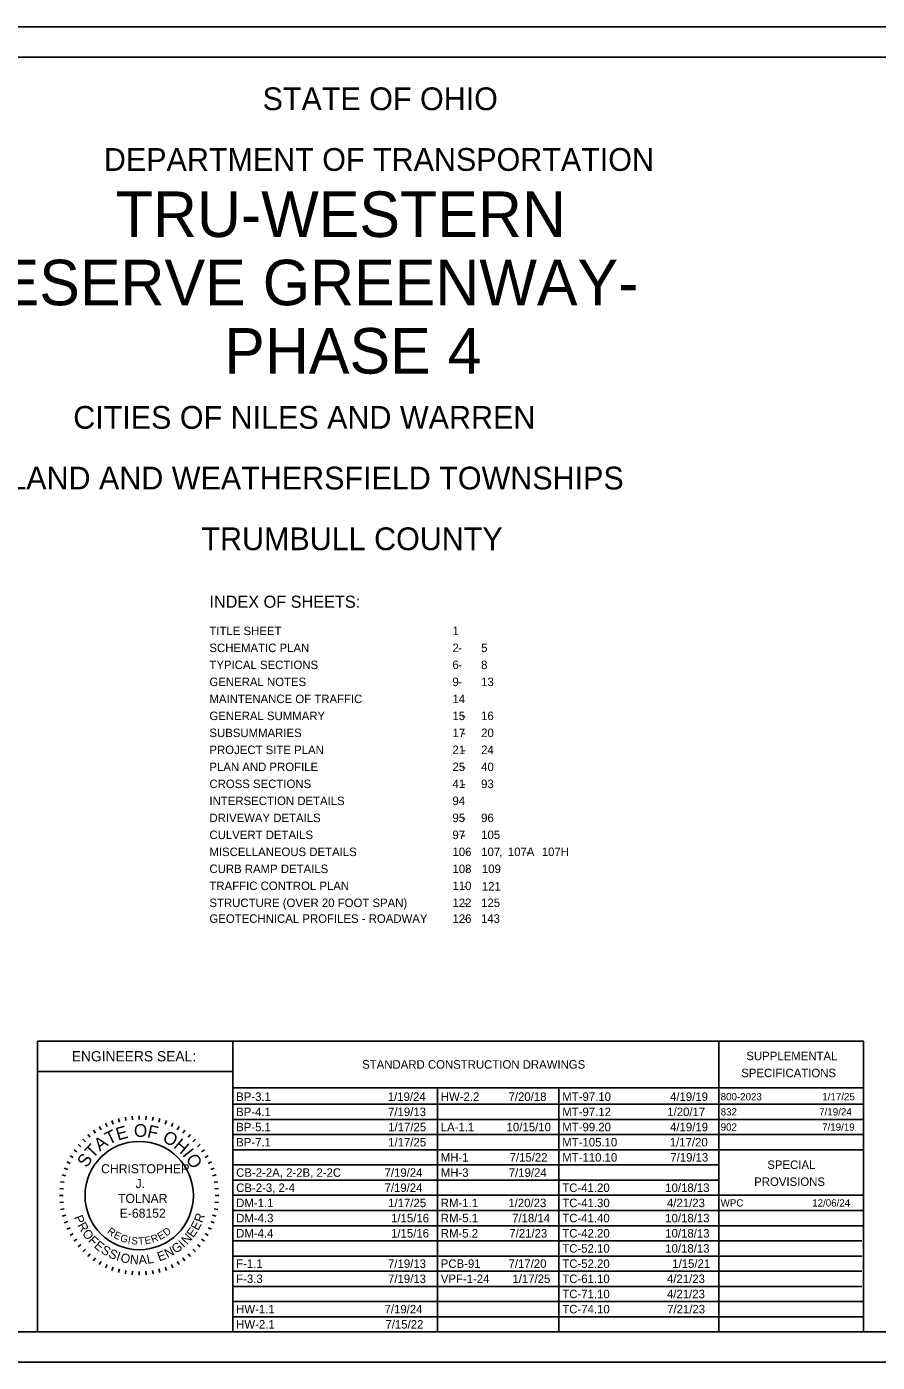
# Model space of a CAD drawing. Extents: x -37878.7 to -37844.7, y -19791.4 to -19769.4.
# Drawn here: x -37867.14 to -37853.14, y -19791.39 to -19769.39 of the extents above; entities that cross this region are included whole.
import ezdxf

# ---------------------------------------------------------------- set-up
doc = ezdxf.new("R2010")
doc.units = 0
for name, color, linetype in [('SH_Border', 7, 'Continuous'), ('SH_Cut_Line', 7, 'Continuous'), ('SH_Data', 7, 'Continuous')]:
    doc.layers.add(name, color=color, linetype=linetype)

msp = doc.modelspace()

# ---------------------------------------------------------------- linework, layer by layer
at = {"layer": 'SH_Border'}
msp.add_lwpolyline([(-37876.65, -19769.885), (-37845.15, -19769.885), (-37845.15, -19790.885), (-37876.65, -19790.885)], close=True, dxfattribs=at)
at = {"layer": 'SH_Cut_Line'}
msp.add_lwpolyline([(-37878.65, -19791.385), (-37844.65, -19791.385), (-37844.65, -19769.385), (-37878.65, -19769.385)], close=True, dxfattribs=at)
at = {"layer": 'SH_Data'}
for p, q in [((-37866.964, -19786.094), (-37863.748, -19786.094)), ((-37866.964, -19787.635), (-37866.964, -19786.094)), ((-37863.748, -19786.094), (-37853.365, -19786.094)), ((-37863.748, -19790.885), (-37863.748, -19786.094)), ((-37855.748, -19790.885), (-37855.748, -19786.094)), ((-37853.365, -19790.885), (-37853.365, -19786.094)), ((-37866.964, -19786.594), (-37863.748, -19786.594)), ((-37863.748, -19786.864), (-37853.365, -19786.864)), ((-37860.38, -19790.885), (-37860.38, -19786.864)), ((-37858.38, -19790.885), (-37858.38, -19786.864)), ((-37863.748, -19787.135), (-37853.365, -19787.135)), ((-37865.844, -19787.449), (-37865.819, -19787.504)), ((-37865.738, -19787.405), (-37865.718, -19787.462)), ((-37865.629, -19787.371), (-37865.614, -19787.429)), ((-37865.517, -19787.346), (-37865.507, -19787.405)), ((-37865.404, -19787.331), (-37865.399, -19787.391)), ((-37865.289, -19787.326), (-37865.289, -19787.386)), ((-37865.175, -19787.331), (-37865.18, -19787.391)), ((-37865.061, -19787.346), (-37865.072, -19787.405)), ((-37864.95, -19787.371), (-37864.965, -19787.429)), ((-37864.84, -19787.405), (-37864.861, -19787.462)), ((-37864.735, -19787.449), (-37864.76, -19787.504)), ((-37863.748, -19787.385), (-37853.365, -19787.385)), ((-37866.964, -19790.885), (-37866.964, -19787.635)), ((-37866.133, -19787.633), (-37866.094, -19787.679)), ((-37866.042, -19787.564), (-37866.008, -19787.613)), ((-37865.946, -19787.502), (-37865.916, -19787.554)), ((-37864.633, -19787.502), (-37864.663, -19787.554)), ((-37864.537, -19787.564), (-37864.571, -19787.613)), ((-37864.446, -19787.633), (-37864.484, -19787.679)), ((-37863.748, -19787.635), (-37853.365, -19787.635)), ((-37866.364, -19787.886), (-37866.315, -19787.92)), ((-37866.295, -19787.795), (-37866.249, -19787.834)), ((-37866.217, -19787.711), (-37866.175, -19787.753)), ((-37864.361, -19787.711), (-37864.404, -19787.753)), ((-37864.284, -19787.795), (-37864.33, -19787.834)), ((-37864.214, -19787.886), (-37864.263, -19787.92)), ((-37863.748, -19787.885), (-37853.365, -19787.885)), ((-37866.479, -19788.084), (-37866.424, -19788.109)), ((-37866.426, -19787.982), (-37866.374, -19788.012)), ((-37864.153, -19787.982), (-37864.205, -19788.012)), ((-37864.1, -19788.084), (-37864.154, -19788.109)), ((-37866.557, -19788.299), (-37866.499, -19788.314)), ((-37866.523, -19788.19), (-37866.466, -19788.21)), ((-37864.056, -19788.19), (-37864.112, -19788.21)), ((-37864.022, -19788.299), (-37864.08, -19788.314)), ((-37863.748, -19788.135), (-37855.748, -19788.135)), ((-37866.597, -19788.524), (-37866.537, -19788.53)), ((-37866.582, -19788.411), (-37866.523, -19788.421)), ((-37863.997, -19788.411), (-37864.056, -19788.421)), ((-37863.982, -19788.524), (-37864.042, -19788.53)), ((-37863.748, -19788.385), (-37855.748, -19788.385)), ((-37866.602, -19788.639), (-37866.542, -19788.639)), ((-37866.597, -19788.753), (-37866.537, -19788.748)), ((-37863.982, -19788.753), (-37864.042, -19788.748)), ((-37863.977, -19788.639), (-37864.037, -19788.639)), ((-37863.748, -19788.635), (-37853.365, -19788.635)), ((-37866.582, -19788.867), (-37866.523, -19788.856)), ((-37866.557, -19788.978), (-37866.499, -19788.963)), ((-37864.022, -19788.978), (-37864.08, -19788.963)), ((-37863.997, -19788.867), (-37864.056, -19788.856)), ((-37863.748, -19788.885), (-37853.365, -19788.885)), ((-37866.523, -19789.088), (-37866.466, -19789.067)), ((-37866.479, -19789.193), (-37866.424, -19789.168)), ((-37864.1, -19789.193), (-37864.154, -19789.168)), ((-37864.056, -19789.088), (-37864.112, -19789.067)), ((-37863.748, -19789.135), (-37853.365, -19789.135)), ((-37866.426, -19789.295), (-37866.374, -19789.265)), ((-37866.364, -19789.391), (-37866.315, -19789.357)), ((-37864.214, -19789.391), (-37864.263, -19789.357)), ((-37864.153, -19789.295), (-37864.205, -19789.265)), ((-37863.748, -19789.385), (-37853.395, -19789.385)), ((-37866.295, -19789.482), (-37866.249, -19789.444)), ((-37866.217, -19789.567), (-37866.175, -19789.524)), ((-37866.133, -19789.644), (-37866.094, -19789.598)), ((-37864.446, -19789.644), (-37864.484, -19789.598)), ((-37864.361, -19789.567), (-37864.404, -19789.524)), ((-37864.284, -19789.482), (-37864.33, -19789.444)), ((-37863.748, -19789.635), (-37853.395, -19789.635)), ((-37866.042, -19789.714), (-37866.008, -19789.665)), ((-37865.946, -19789.775), (-37865.916, -19789.723)), ((-37865.844, -19789.828), (-37865.819, -19789.774)), ((-37865.738, -19789.872), (-37865.718, -19789.816)), ((-37865.629, -19789.906), (-37865.614, -19789.848)), ((-37865.517, -19789.931), (-37865.507, -19789.872)), ((-37865.061, -19789.931), (-37865.072, -19789.872)), ((-37864.95, -19789.906), (-37864.965, -19789.848)), ((-37864.84, -19789.872), (-37864.861, -19789.816)), ((-37864.735, -19789.828), (-37864.76, -19789.774)), ((-37864.633, -19789.775), (-37864.663, -19789.723)), ((-37864.537, -19789.714), (-37864.571, -19789.665)), ((-37865.404, -19789.946), (-37865.399, -19789.886)), ((-37865.289, -19789.951), (-37865.289, -19789.891)), ((-37865.175, -19789.946), (-37865.18, -19789.886)), ((-37863.748, -19789.885), (-37853.395, -19789.885)), ((-37863.748, -19790.135), (-37853.395, -19790.135)), ((-37863.748, -19790.385), (-37853.365, -19790.385)), ((-37863.748, -19790.635), (-37853.365, -19790.635))]:
    msp.add_line(p, q, dxfattribs=at)
msp.add_circle((-37865.289, -19788.639), 0.892, dxfattribs=at)

# ---------------------------------------------------------------- texts
for s, height, p in [('STATE OF OHIO', 0.375, (-37863.258, -19770.76)), ('DEPARTMENT OF TRANSPORTATION', 0.375, (-37865.87, -19771.76)), ('TRU-WESTERN', 0.75, (-37865.676, -19772.849)), ('RESERVE GREENWAY-', 0.75, (-37868.328, -19773.974)), ('PHASE 4', 0.75, (-37863.89, -19775.099)), ('CITIES OF NILES AND WARREN', 0.375, (-37866.375, -19776.008)), ('HOWLAND AND WEATHERSFIELD TOWNSHIPS', 0.375, (-37868.653, -19777.008)), ('TRUMBULL COUNTY', 0.375, (-37864.265, -19778.008)), ('INDEX OF SHEETS:', 0.2, (-37864.133, -19778.957)), ('TITLE SHEET', 0.14, (-37864.133, -19779.407)), ('1', 0.14, (-37860.133, -19779.407)), ('SCHEMATIC PLAN', 0.14, (-37864.133, -19779.687)), ('2', 0.14, (-37860.133, -19779.687)), ('   -', 0.14, (-37860.196, -19779.687)), ('5', 0.14, (-37859.661, -19779.687)), ('TYPICAL SECTIONS', 0.14, (-37864.133, -19779.967)), ('6', 0.14, (-37860.133, -19779.967)), ('   -', 0.14, (-37860.196, -19779.967)), ('8', 0.14, (-37859.661, -19779.967)), ('GENERAL NOTES', 0.14, (-37864.133, -19780.247)), ('9', 0.14, (-37860.133, -19780.247)), ('   -', 0.14, (-37860.196, -19780.247)), ('13', 0.14, (-37859.661, -19780.247)), ('MAINTENANCE OF TRAFFIC', 0.14, (-37864.133, -19780.527)), ('14', 0.14, (-37860.133, -19780.527)), ('GENERAL SUMMARY', 0.14, (-37864.133, -19780.807)), ('15', 0.14, (-37860.133, -19780.807)), ('   -', 0.14, (-37860.133, -19780.807)), ('16', 0.14, (-37859.661, -19780.807)), ('SUBSUMMARIES', 0.14, (-37864.133, -19781.087)), ('17', 0.14, (-37860.133, -19781.087)), ('   -', 0.14, (-37860.133, -19781.087)), ('20', 0.14, (-37859.661, -19781.087)), ('PROJECT SITE PLAN', 0.14, (-37864.133, -19781.367)), ('21', 0.14, (-37860.133, -19781.367)), ('24', 0.14, (-37859.661, -19781.367)), ('PLAN AND PROFILE', 0.14, (-37864.133, -19781.647)), ('25', 0.14, (-37860.133, -19781.647)), ('   -', 0.14, (-37860.133, -19781.367)), ('40', 0.14, (-37859.661, -19781.647)), ('   -', 0.14, (-37860.133, -19781.647)), ('CROSS SECTIONS', 0.14, (-37864.133, -19781.927)), ('41', 0.14, (-37860.133, -19781.927)), ('   -', 0.14, (-37860.133, -19781.927)), ('93', 0.14, (-37859.661, -19781.927)), ('INTERSECTION DETAILS', 0.14, (-37864.133, -19782.207)), ('94', 0.14, (-37860.133, -19782.207)), ('DRIVEWAY DETAILS', 0.14, (-37864.133, -19782.487)), ('95', 0.14, (-37860.133, -19782.487)), ('96', 0.14, (-37859.661, -19782.487)), ('   -', 0.14, (-37860.133, -19782.487)), ('CULVERT DETAILS', 0.14, (-37864.133, -19782.767)), ('97', 0.14, (-37860.133, -19782.767)), ('   -', 0.14, (-37860.133, -19782.767)), ('105', 0.14, (-37859.661, -19782.767)), ('MISCELLANEOUS DETAILS', 0.14, (-37864.133, -19783.047)), ('106', 0.14, (-37860.133, -19783.047)), ('   -', 0.14, (-37860.082, -19783.047)), ('107', 0.14, (-37859.659, -19783.047)), (',', 0.14, (-37859.364, -19783.047)), ('107A', 0.14, (-37859.221, -19783.047)), ('   -', 0.14, (-37859.077, -19783.047)), ('107H', 0.14, (-37858.663, -19783.047)), ('CURB RAMP DETAILS', 0.14, (-37864.133, -19783.327)), ('108', 0.14, (-37860.133, -19783.327)), ('   -', 0.14, (-37860.082, -19783.327)), ('109', 0.14, (-37859.648, -19783.327)), ('TRAFFIC CONTROL PLAN', 0.14, (-37864.133, -19783.607)), ('110', 0.14, (-37860.133, -19783.607)), ('121', 0.14, (-37859.648, -19783.615)), ('   -', 0.14, (-37860.107, -19783.607)), ('STRUCTURE (OVER 20 FOOT SPAN)', 0.14, (-37864.133, -19783.887)), ('122', 0.14, (-37860.133, -19783.887)), ('   -', 0.14, (-37860.105, -19783.887)), ('125', 0.14, (-37859.661, -19783.887)), ('GEOTECHNICAL PROFILES - ROADWAY', 0.14, (-37864.133, -19784.147)), ('126', 0.14, (-37860.133, -19784.147)), ('   -', 0.14, (-37860.103, -19784.147)), ('143', 0.14, (-37859.663, -19784.147)), ('ENGINEERS SEAL:', 0.17, (-37866.399, -19786.429)), ('SUPPLEMENTAL', 0.14, (-37855.295, -19786.409)), ('STANDARD CONSTRUCTION DRAWINGS', 0.14, (-37861.619, -19786.549)), ('SPECIFICATIONS', 0.14, (-37855.379, -19786.689)), ('BP-3.1', 0.14, (-37863.693, -19787.08)), ('1/19/24', 0.14, (-37861.198, -19787.08)), ('HW-2.2', 0.14, (-37860.325, -19787.08)), ('7/20/18', 0.14, (-37859.21, -19787.08)), ('MT-97.10', 0.14, (-37858.325, -19787.08)), ('4/19/19', 0.14, (-37856.551, -19787.08)), ('800-2023', 0.12, (-37855.718, -19787.07)), ('1/17/25', 0.12, (-37854.045, -19787.07)), ('BP-4.1', 0.14, (-37863.693, -19787.33)), ('7/19/13', 0.14, (-37861.193, -19787.33)), ('MT-97.12', 0.14, (-37858.325, -19787.33)), ('1/20/17', 0.14, (-37856.597, -19787.33)), ('832', 0.12, (-37855.718, -19787.32)), ('7/19/24', 0.12, (-37854.096, -19787.32)), ('BP-5.1', 0.14, (-37863.693, -19787.58)), ('1/17/25', 0.14, (-37861.191, -19787.58)), ('LA-1.1', 0.14, (-37860.325, -19787.58)), ('10/15/10', 0.14, (-37859.241, -19787.58)), ('MT-99.20', 0.14, (-37858.325, -19787.58)), ('4/19/19', 0.14, (-37856.551, -19787.58)), ('902', 0.12, (-37855.718, -19787.57)), ('7/19/19', 0.12, (-37854.048, -19787.57)), ('BP-7.1', 0.14, (-37863.693, -19787.83)), ('1/17/25', 0.14, (-37861.191, -19787.83)), ('MT-105.10', 0.14, (-37858.325, -19787.83)), ('1/17/20', 0.14, (-37856.556, -19787.83)), ('MH-1', 0.14, (-37860.325, -19788.08)), ('7/15/22', 0.14, (-37859.192, -19788.08)), ('MT-110.10', 0.14, (-37858.325, -19788.08)), ('7/19/13', 0.14, (-37856.547, -19788.08)), ('SPECIAL', 0.14, (-37854.95, -19788.201)), ('CHRISTOPHER', 0.15, (-37865.916, -19788.273)), ('CB-2-2A, 2-2B, 2-2C', 0.14, (-37863.693, -19788.33)), ('7/19/24', 0.14, (-37861.251, -19788.33)), ('MH-3', 0.14, (-37860.325, -19788.33)), ('7/19/24', 0.14, (-37859.206, -19788.33)), ('PROVISIONS', 0.14, (-37855.166, -19788.481)), ('J.', 0.15, (-37865.349, -19788.517)), ('CB-2-3, 2-4', 0.14, (-37863.693, -19788.58)), ('7/19/24', 0.14, (-37861.251, -19788.58)), ('TC-41.20', 0.14, (-37858.325, -19788.58)), ('10/18/13', 0.14, (-37856.63, -19788.58)), ('TOLNAR', 0.15, (-37865.637, -19788.761)), ('DM-1.1', 0.14, (-37863.693, -19788.83)), ('1/17/25', 0.14, (-37861.191, -19788.83)), ('RM-1.1', 0.14, (-37860.325, -19788.83)), ('1/20/23', 0.14, (-37859.213, -19788.83)), ('TC-41.30', 0.14, (-37858.325, -19788.83)), ('4/21/23', 0.14, (-37856.602, -19788.83)), ('WPC', 0.12, (-37855.718, -19788.82)), ('12/06/24', 0.12, (-37854.211, -19788.82)), ('E-68152', 0.15, (-37865.61, -19789.004)), ('DM-4.3', 0.14, (-37863.693, -19789.08)), ('1/15/16', 0.14, (-37861.143, -19789.08)), ('RM-5.1', 0.14, (-37860.325, -19789.08)), ('7/18/14', 0.14, (-37859.151, -19789.08)), ('TC-41.40', 0.14, (-37858.325, -19789.08)), ('10/18/13', 0.14, (-37856.63, -19789.08)), ('DM-4.4', 0.14, (-37863.693, -19789.33)), ('1/15/16', 0.14, (-37861.143, -19789.33)), ('RM-5.2', 0.14, (-37860.325, -19789.33)), ('7/21/23', 0.14, (-37859.197, -19789.33)), ('TC-42.20', 0.14, (-37858.325, -19789.33)), ('10/18/13', 0.14, (-37856.63, -19789.33)), ('TC-52.10', 0.14, (-37858.325, -19789.58)), ('10/18/13', 0.14, (-37856.63, -19789.58)), ('F-1.1', 0.14, (-37863.693, -19789.83)), ('7/19/13', 0.14, (-37861.193, -19789.83)), ('PCB-91', 0.14, (-37860.325, -19789.83)), ('7/17/20', 0.14, (-37859.21, -19789.83)), ('TC-52.20', 0.14, (-37858.325, -19789.83)), ('1/15/21', 0.14, (-37856.515, -19789.83)), ('F-3.3', 0.14, (-37863.693, -19790.08)), ('7/19/13', 0.14, (-37861.193, -19790.08)), ('VPF-1-24', 0.14, (-37860.325, -19790.08)), ('1/17/25', 0.14, (-37859.146, -19790.08)), ('TC-61.10', 0.14, (-37858.325, -19790.08)), ('4/21/23', 0.14, (-37856.602, -19790.08)), ('TC-71.10', 0.14, (-37858.325, -19790.33)), ('4/21/23', 0.14, (-37856.602, -19790.33)), ('HW-1.1', 0.14, (-37863.693, -19790.58)), ('7/19/24', 0.14, (-37861.251, -19790.58)), ('TC-74.10', 0.14, (-37858.325, -19790.58)), ('7/21/23', 0.14, (-37856.599, -19790.58)), ('HW-2.1', 0.14, (-37863.693, -19790.83)), ('7/15/22', 0.14, (-37861.236, -19790.83))]:
    msp.add_text(s, height=height, dxfattribs=at).set_placement(p)
for s, height, rotation, p in [('O', 0.21, 359.7812, (-37865.376, -19787.672)), ('T', 0.21, 25.7167, (-37865.79, -19787.808)), ('E', 0.21, 15.7571, (-37865.639, -19787.734)), ('F', 0.21, 347.4362, (-37865.168, -19787.676)), ('O', 0.21, 332.2586, (-37864.92, -19787.741)), ('T', 0.21, 46.4344, (-37866.052, -19788.039)), ('A', 0.21, 36.4747, (-37865.937, -19787.916)), ('H', 0.21, 319.9136, (-37864.737, -19787.841)), ('I', 0.21, 308.367, (-37864.588, -19787.968)), ('S', 0.21, 57.1924, (-37866.15, -19788.191)), ('O', 0.21, 303.1491, (-37864.53, -19788.035)), ('P', 0.15, 291.494, (-37866.366, -19788.996)), ('R', 0.15, 69.2322, (-37864.252, -19789.098)), ('R', 0.15, 298.7311, (-37866.312, -19789.129)), ('O', 0.15, 306.4666, (-37866.237, -19789.262)), ('R', 0.12, 323.2378, (-37865.825, -19789.248)), ('D', 0.12, 38.0378, (-37864.842, -19789.315)), ('E', 0.15, 54.758, (-37864.4, -19789.343)), ('E', 0.15, 61.9951, (-37864.319, -19789.225)), ('F', 0.15, 314.7068, (-37866.138, -19789.391)), ('E', 0.15, 321.4393, (-37866.044, -19789.486)), ('E', 0.12, 332.4256, (-37865.721, -19789.325)), ('G', 0.12, 341.0076, (-37865.614, -19789.382)), ('I', 0.12, 350.8085, (-37865.482, -19789.426)), ('S', 0.12, 355.1352, (-37865.423, -19789.439)), ('T', 0.12, 3.7172, (-37865.302, -19789.45)), ('E', 0.12, 11.686, (-37865.189, -19789.444)), ('R', 0.12, 20.268, (-37865.07, -19789.42)), ('E', 0.12, 29.4558, (-37864.948, -19789.375)), ('G', 0.15, 35.0469, (-37864.69, -19789.601)), ('I', 0.15, 43.287, (-37864.558, -19789.506)), ('N', 0.15, 47.0224, (-37864.503, -19789.456)), ('S', 0.15, 328.6764, (-37865.931, -19789.574)), ('S', 0.15, 335.9134, (-37865.808, -19789.647)), ('I', 0.15, 343.1505, (-37865.677, -19789.705)), ('O', 0.15, 346.8859, (-37865.607, -19789.728)), ('N', 0.15, 355.1261, (-37865.447, -19789.762)), ('A', 0.15, 2.8617, (-37865.295, -19789.773)), ('L', 0.15, 10.0987, (-37865.152, -19789.765)), ('E', 0.15, 20.0742, (-37864.959, -19789.724)), ('N', 0.15, 27.3113, (-37864.825, -19789.673))]:
    msp.add_text(s, height=height, rotation=rotation, dxfattribs=at).set_placement(p)

doc.saveas('drawing.dxf')
